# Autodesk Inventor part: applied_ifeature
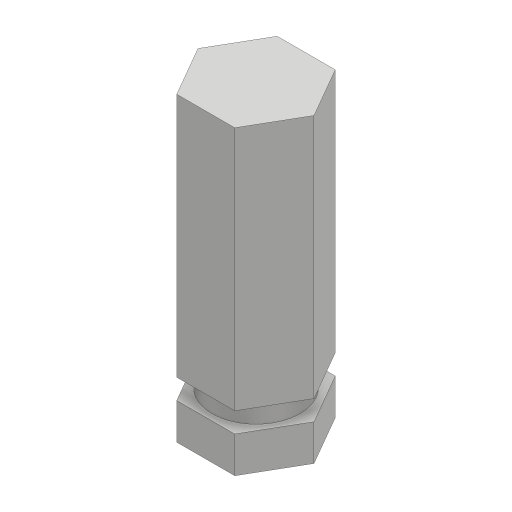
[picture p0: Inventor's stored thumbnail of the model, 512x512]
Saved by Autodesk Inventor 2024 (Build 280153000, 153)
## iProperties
Created: 2016-08
Part Number: applied_ifeature
Material: Generic
Document SubType Name: Modeling
Designer: Sandeep
Density: 1 g/cm^3
Appearance: Default
Author: Sandeep
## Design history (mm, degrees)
sketch "Sketch1"
  geometry: L1 (28.868, 0)-(14.434, -25); L2 (14.434, -25)-(-14.434, -25); L3 (-14.434, -25)-(-28.868, 0); L4 (-28.868, 0)-(-14.434, 25); L5 (-14.434, 25)-(14.434, 25); L6 (14.434, 25)-(28.868, 0); 2 further points
  constraints: 12 end point, 1 coincident, 13 other
  dimensions: "d0" = 50 distance between parallel lines of L2 L5
extrude "Extrusion1" new body sketch "Sketch1" distance "d1" = 150; taper "d2" = 0 deg
feature "iFeature4:1"
body "Solid1"
